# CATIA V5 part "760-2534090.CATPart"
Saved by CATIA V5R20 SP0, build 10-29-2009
Part number: 760-2534090
Source: Unknown
Property "A": "30.000"
Property "ARTICLENO": "760-2534090"
Property "BOMINFO": "760-2534090"
Property "CODE": "760-2534090"
Property "K": "62.500"
Property "L": "125.000"
Property "LINA": "760-2534090"
Property "NB": "760-2534090"
Property "NBSYN": "$CODE."
Property "NN": "760"
Property "NT": "Key"
Property "SUPPLIER": "CF"
Bounding box of the stored display mesh (mm): x -62.5 to 62.5, y 0 to 30, z -15 to 15
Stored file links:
  C:\Users\Utente\Desktop\3D files 760\760-2534090.CATPart
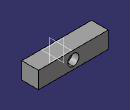
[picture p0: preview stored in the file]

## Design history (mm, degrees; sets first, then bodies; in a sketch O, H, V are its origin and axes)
Body1 "Geometry.1" (main body)
  Solid1 "760-2534090.catpart": solid without history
